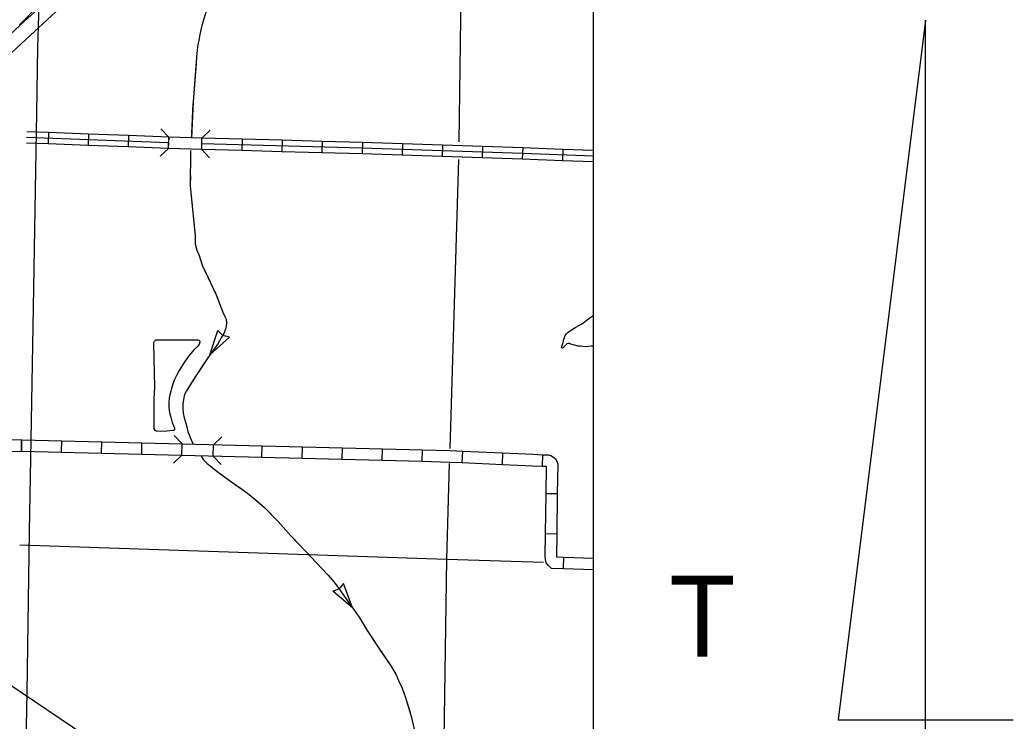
# Model space of a CAD drawing. Extents: x 1196286 to 1268366, y 2040822 to 2082115.
# Drawn here: x 1238759 to 1243663, y 2060409 to 2063873 of the extents above; entities that cross this region are included whole.
import ezdxf

# ---------------------------------------------------------------- set-up
doc = ezdxf.new("R2010")
doc.units = 0
for name, color, linetype in [('26', 7, 'Continuous'), ('60', 7, 'Continuous'), ('61', 7, 'Continuous'), ('62', 7, 'Continuous'), ('Level 71', 7, 'Continuous'), ('Level 8', 7, 'Continuous'), ('Level 81', 7, 'Continuous'), ('Level 83', 7, 'Continuous'), ('Level 84', 7, 'Continuous'), ('Level 87', 7, 'Continuous')]:
    doc.layers.add(name, color=color, linetype=linetype)

msp = doc.modelspace()

# ---------------------------------------------------------------- linework, layer by layer
at = {"layer": '60'}
for points in [[(1240928, 2063270.6), (1240953.2, 2065222)], [(1240882.7, 2061755.5), (1240926.1, 2063183.4)], [(1240836.4, 2059202.8), (1240866.1, 2061210.1), (1240880.5, 2061681.6)], [(1238758.7, 2061280.6), (1240866.1, 2061210.1), (1241344.8, 2061194.4)]]:
    msp.add_lwpolyline(points, dxfattribs=at)
at = {"layer": '61'}
for p, q in [((1238900.1, 2063316.3), (1238898, 2063260.1)), ((1239097.9, 2063308.9), (1239095.8, 2063252.7)), ((1239295.8, 2063301.4), (1239293.7, 2063245.2)), ((1239493.7, 2063294), (1239491.5, 2063237.8)), ((1239855.8, 2063283.7), (1239854.2, 2063227.4)), ((1240053.8, 2063278), (1240052.2, 2063221.8)), ((1240251.7, 2063272.4), (1240250.1, 2063216.1)), ((1240449.6, 2063266.7), (1240448, 2063210.5)), ((1240647.6, 2063260.3), (1240645.8, 2063204.1)), ((1240845.5, 2063253.9), (1240843.7, 2063197.6)), ((1241043.4, 2063247.4), (1241041.6, 2063191.2)), ((1241241.3, 2063241), (1241239.5, 2063184.8)), ((1241439.3, 2063233.4), (1241437.1, 2063177.2)), ((1238766.4, 2061742.2), (1238767.8, 2061798.4)), ((1238964.3, 2061737.2), (1238965.7, 2061793.5)), ((1239162.2, 2061732.3), (1239163.6, 2061788.5)), ((1239360.2, 2061727.3), (1239361.6, 2061783.6)), ((1239558.1, 2061722.4), (1239559.5, 2061778.6)), ((1239713.3, 2061718.1), (1239714.7, 2061774.4)), ((1239954, 2061712.5), (1239955.4, 2061768.7)), ((1240151.9, 2061707.5), (1240153.3, 2061763.7)), ((1240349.9, 2061702.5), (1240351.3, 2061758.8)), ((1240547.8, 2061697.6), (1240549.2, 2061753.8)), ((1240745.7, 2061692.6), (1240747.1, 2061748.9)), ((1240943.1, 2061686.5), (1240945.6, 2061742.7)), ((1241140.9, 2061677.6), (1241143.4, 2061733.8)), ((1241338.9, 2061669.1), (1241341, 2061725.3)), ((1241355.9, 2061533.9), (1241412.1, 2061533.1)), ((1241352.9, 2061336), (1241409.1, 2061335.1)), ((1241442.6, 2061163.1), (1241444.4, 2061219.3))]:
    msp.add_line(p, q, dxfattribs=at)
for points in [[(1239492.6, 2063265.9), (1238791.8, 2063292.2)], [(1238900.1, 2063316.3), (1238792.9, 2063320.3)], [(1239097.9, 2063308.9), (1238900.1, 2063316.3)], [(1239295.8, 2063301.4), (1239097.9, 2063308.9)], [(1239493.7, 2063294), (1239295.8, 2063301.4)], [(1239491.8, 2063237.8), (1239493.4, 2063294)], [(1239657.9, 2063289.3), (1239493.4, 2063294)], [(1239656.3, 2063233.1), (1239657.9, 2063289.3)], [(1239855.8, 2063283.7), (1239657.9, 2063289.3)], [(1240053.8, 2063278), (1239855.8, 2063283.7)], [(1240251.7, 2063272.4), (1240053.8, 2063278)], [(1240449.6, 2063266.7), (1240251.7, 2063272.4)], [(1238898, 2063260.1), (1238790.8, 2063264.1)], [(1239095.8, 2063252.7), (1238898, 2063260.1)], [(1239293.7, 2063245.2), (1239095.8, 2063252.7)], [(1239491.5, 2063237.8), (1239293.7, 2063245.2)], [(1239656.3, 2063233.1), (1239491.8, 2063237.8)], [(1239854.2, 2063227.4), (1239656.3, 2063233.1)], [(1241590.6, 2063199.4), (1241240.4, 2063212.9), (1240448.8, 2063238.6), (1239657.1, 2063261.2)], [(1240052.2, 2063221.8), (1239854.2, 2063227.4)], [(1240647.6, 2063260.3), (1240449.9, 2063266.7), (1240450, 2063266.7)], [(1240845.5, 2063253.9), (1240647.6, 2063260.3)], [(1241043.4, 2063247.4), (1240845.5, 2063253.9)], [(1241241.3, 2063241), (1241043.4, 2063247.4)], [(1241439.3, 2063233.4), (1241241.5, 2063241)], [(1241590.6, 2063227.5), (1241439.3, 2063233.4)], [(1240250.1, 2063216.1), (1240052.2, 2063221.8)], [(1240448, 2063210.5), (1240250.1, 2063216.1)], [(1240645.8, 2063204.1), (1240447.7, 2063210.5), (1240447.6, 2063210.5)], [(1240843.7, 2063197.6), (1240645.8, 2063204.1)], [(1241041.6, 2063191.2), (1240843.7, 2063197.6)], [(1241239.5, 2063184.8), (1241041.6, 2063191.2)], [(1241437.1, 2063177.2), (1241239.3, 2063184.8)], [(1241590.6, 2063171.2), (1241437.1, 2063177.2)], [(1238767.8, 2061798.4), (1238965.7, 2061793.5)], [(1238965.7, 2061793.5), (1239163.6, 2061788.5)], [(1239163.6, 2061788.5), (1239361.6, 2061783.6)], [(1239361.6, 2061783.6), (1239559.5, 2061778.6)], [(1239559.5, 2061778.6), (1239757.5, 2061773.6)], [(1239757.5, 2061773.6), (1239955.4, 2061768.7)], [(1239955.4, 2061768.7), (1240153.3, 2061763.7)], [(1240153.3, 2061763.7), (1240351.3, 2061758.8)], [(1240351.3, 2061758.8), (1240549.2, 2061753.8)], [(1240549.2, 2061753.8), (1240747.1, 2061748.9)], [(1238766.4, 2061742.2), (1238964.3, 2061737.2)], [(1238964.3, 2061737.2), (1239162.2, 2061732.3)], [(1239162.2, 2061732.3), (1239360.2, 2061727.3)], [(1239360.2, 2061727.3), (1239558.1, 2061722.4)], [(1239558.1, 2061722.4), (1239756, 2061717.4)], [(1239756, 2061717.4), (1239954, 2061712.5)], [(1239954, 2061712.5), (1240151.9, 2061707.5)], [(1240151.9, 2061707.5), (1240349.9, 2061702.5)], [(1240349.9, 2061702.5), (1240547.8, 2061697.6)], [(1240747.1, 2061748.9), (1240884, 2061745.4), (1240945.6, 2061742.7)], [(1240945.6, 2061742.7), (1241143.4, 2061733.8)], [(1241143.4, 2061733.8), (1241291.6, 2061727.1), (1241341, 2061725.3)], [(1241341, 2061725.3), (1241366.5, 2061724.3), (1241384, 2061719.8), (1241395.5, 2061710.9), (1241402.7, 2061704.3), (1241409.6, 2061693.6), (1241414.3, 2061678.8), (1241412.1, 2061533.1)], [(1240547.8, 2061697.6), (1240745.7, 2061692.6)], [(1240745.7, 2061692.6), (1240882, 2061689.2), (1240943.1, 2061686.5)], [(1240943.1, 2061686.5), (1241140.9, 2061677.6)], [(1241140.9, 2061677.6), (1241289.3, 2061670.9), (1241338.9, 2061669.1)], [(1241338.9, 2061669.1), (1241357.9, 2061668.4), (1241355.9, 2061533.9)], [(1241355.9, 2061533.9), (1241352.9, 2061336)], [(1241412.1, 2061533.1), (1241409.1, 2061335.1)], [(1241352.9, 2061336), (1241351.1, 2061222.4), (1241351.9, 2061208), (1241355.5, 2061191.1), (1241365.9, 2061180.4), (1241381.7, 2061165.1), (1241442.6, 2061163.1)], [(1241409.1, 2061335.1), (1241407.4, 2061223.5), (1241407.6, 2061220.5), (1241444.4, 2061219.3)], [(1241444.4, 2061219.3), (1241590.6, 2061214.5)], [(1241442.6, 2061163.1), (1241590.6, 2061158.2)]]:
    msp.add_lwpolyline(points, dxfattribs=at)
at = {"layer": '62'}
for p, q in [((1239696.4, 2062218.5), (1239735.8, 2062339.4)), ((1239696.4, 2062218.5), (1239793.1, 2062305.3)), ((1239735.8, 2062339.4), (1239759.7, 2062314.9)), ((1239793.1, 2062305.3), (1239760.1, 2062314.7)), ((1240356, 2061089.5), (1240334.6, 2061062.9)), ((1240401.3, 2060968.6), (1240357, 2061089.5)), ((1240303.2, 2061050.6), (1240334.2, 2061062.6)), ((1240401.3, 2060968.6), (1240303.2, 2061050.6))]:
    msp.add_line(p, q, dxfattribs=at)
for points in [[(1239749.7, 2064160.6), (1239733.5, 2064109.1), (1239690.6, 2063954.2), (1239656.8, 2063845.1), (1239646.5, 2063801.2), (1239642.1, 2063772.6), (1239638.1, 2063749.3), (1239633.2, 2063710.3), (1239613.6, 2063468.2), (1239606, 2063290.9)], [(1239749.7, 2064160.6), (1239733.5, 2064109.1), (1239690.6, 2063954.2), (1239656.8, 2063845.1), (1239646.5, 2063801.2), (1239642.1, 2063772.6), (1239638.1, 2063749.3), (1239633.2, 2063710.3), (1239613.6, 2063468.2), (1239606, 2063290.9)], [(1239658.9, 2063852), (1239656.8, 2063845.1), (1239646.5, 2063801.2), (1239642.1, 2063772.6), (1239638.1, 2063749.3), (1239633.2, 2063710.3), (1239632.8, 2063706)], [(1239628.8, 2063656.6), (1239616.8, 2063508.6)], [(1239613.2, 2063459.3), (1239606.8, 2063310.9)], [(1239601.8, 2063228), (1239600.2, 2063051.8), (1239624.7, 2062806.4), (1239624.6, 2062767.3), (1239631.8, 2062736), (1239643.8, 2062708.8), (1239659, 2062661.6), (1239728.6, 2062514.9), (1239761.4, 2062428.8), (1239770.5, 2062408.3), (1239776.4, 2062394.4), (1239778.8, 2062375.9), (1239777.1, 2062357.9), (1239774, 2062345.5), (1239765.5, 2062324.1), (1239752.1, 2062301.7), (1239735.7, 2062273.3), (1239686.2, 2062204.2), (1239628.7, 2062116.1), (1239581.4, 2062041), (1239574.9, 2062029.8), (1239569.8, 2062015.2), (1239567, 2061996.8), (1239562.7, 2061977.6), (1239562.8, 2061955), (1239564.4, 2061930.9), (1239569.4, 2061907.2), (1239578.5, 2061880.4), (1239587.8, 2061839.7), (1239603.8, 2061798.5), (1239613.2, 2061780.3)], [(1239601.8, 2063228), (1239600.2, 2063051.8), (1239624.7, 2062806.4), (1239624.6, 2062767.3), (1239631.8, 2062736), (1239643.8, 2062708.8), (1239659, 2062661.6), (1239728.6, 2062514.9), (1239761.4, 2062428.8), (1239770.5, 2062408.3), (1239776.4, 2062394.4), (1239778.8, 2062375.9), (1239777.1, 2062357.9), (1239774, 2062345.5), (1239765.5, 2062324.1), (1239752.1, 2062301.7), (1239735.7, 2062273.3), (1239686.2, 2062204.2), (1239628.7, 2062116.1), (1239581.4, 2062041), (1239574.9, 2062029.8), (1239569.8, 2062015.2), (1239567, 2061996.8), (1239562.7, 2061977.6), (1239562.8, 2061955), (1239564.4, 2061930.9), (1239569.4, 2061907.2), (1239578.5, 2061880.4), (1239587.8, 2061839.7), (1239603.8, 2061798.5), (1239613.2, 2061780.3)], [(1239601.8, 2063228), (1239601.1, 2063153.7)], [(1239600.7, 2063104.2), (1239600.2, 2063051.8), (1239609.7, 2062956.2)], [(1239614.6, 2062907), (1239624.7, 2062806.4), (1239624.6, 2062767.3), (1239626.5, 2062759.2)], [(1239642.2, 2062712.5), (1239643.8, 2062708.8), (1239659, 2062661.6), (1239699.7, 2062575.9)], [(1239720.9, 2062531.1), (1239728.6, 2062514.9), (1239761.4, 2062428.8), (1239770.5, 2062408.3), (1239776.4, 2062394.4), (1239776.5, 2062393.5)], [(1241590.6, 2062260.7), (1241579.2, 2062260.5), (1241553.7, 2062258.6), (1241525.6, 2062260.7), (1241515.9, 2062261.6), (1241497.6, 2062265.9), (1241490.9, 2062267.5), (1241478.6, 2062271.8), (1241476.3, 2062272.9), (1241472.6, 2062273.7), (1241470.7, 2062274.1), (1241467.3, 2062274.5), (1241464, 2062274.2), (1241461.3, 2062273.1), (1241456, 2062270.1), (1241454.2, 2062267.9), (1241451.1, 2062264.5), (1241449.2, 2062262.3), (1241446.6, 2062259), (1241443.9, 2062256), (1241442.4, 2062254.9), (1241441.2, 2062253.4), (1241435.6, 2062251.2), (1241433.4, 2062254.2), (1241434.6, 2062259.5), (1241437.3, 2062269.6), (1241440.8, 2062278.6), (1241442.7, 2062286.5), (1241444.7, 2062295.8), (1241447.4, 2062304.8), (1241451.3, 2062313.5), (1241457.4, 2062322), (1241466.1, 2062330.6), (1241480.1, 2062340.2), (1241504.2, 2062355.8), (1241515.5, 2062362), (1241533.6, 2062371.2), (1241552.1, 2062384.6), (1241570.3, 2062399.1), (1241590.6, 2062413.1)], [(1239773.7, 2062344.7), (1239765.5, 2062324.1), (1239752.1, 2062301.7), (1239735.7, 2062273.3), (1239719, 2062249.9)], [(1239424.2, 2062058.2), (1239420.3, 2062273.9), (1239420, 2062276.5), (1239420.4, 2062279.5), (1239421.6, 2062282.9), (1239422.7, 2062285.5), (1239424.2, 2062287.8), (1239430.7, 2062292.2), (1239435.5, 2062292.5), (1239451.3, 2062292.4), (1239549.8, 2062292.4), (1239622.1, 2062292.8), (1239627, 2062292.7), (1239633.8, 2062292.3), (1239637.9, 2062291.8), (1239642.7, 2062291.4), (1239643.9, 2062290.3), (1239645, 2062288), (1239646.4, 2062286.1), (1239647.1, 2062282), (1239646.3, 2062277.8), (1239645.2, 2062274.1), (1239641.3, 2062266.6), (1239634.9, 2062259.1), (1239621.6, 2062245.7), (1239590.5, 2062212.2), (1239567.3, 2062175.2), (1239545.2, 2062141.6), (1239534, 2062119.2), (1239522.5, 2062096.3), (1239515.6, 2062079.1), (1239511.7, 2062068.2), (1239507.1, 2062051.7), (1239503.2, 2062038.6), (1239499.2, 2062021.4), (1239495.7, 2062003.7), (1239494.3, 2061985.3), (1239494.4, 2061959), (1239497.5, 2061933), (1239504, 2061910), (1239510.5, 2061884.7), (1239517, 2061869.9), (1239521.1, 2061861.3), (1239522.9, 2061857.5), (1239522.9, 2061856.3), (1239522.8, 2061849.6), (1239520.5, 2061845.5), (1239513.8, 2061844), (1239485.6, 2061841.3), (1239450.8, 2061840.2), (1239436.5, 2061842.2), (1239431.7, 2061842.3), (1239426.1, 2061844.2), (1239422, 2061852.9), (1239421.5, 2061868.3), (1239421.7, 2061923.6), (1239421.7, 2061956.7), (1239422.1, 2062001.2), (1239424.2, 2062058.2)], [(1239668.7, 2062177.5), (1239628.7, 2062116.1), (1239628.2, 2062115.3)], [(1239628.2, 2062115.3), (1239588.6, 2062052.5)], [(1239568.7, 2062007.7), (1239567, 2061996.8), (1239562.7, 2061977.6), (1239562.8, 2061955), (1239564.4, 2061930.9), (1239569.4, 2061907.2), (1239578.5, 2061880.4), (1239582.6, 2061862.4)], [(1239597.3, 2061815.2), (1239603.8, 2061798.5), (1239613.2, 2061780.3)], [(1239654, 2061717.8), (1239664.2, 2061702.3), (1239684.2, 2061681.8), (1239731.4, 2061643.3), (1239793.8, 2061597.1), (1239882.7, 2061535.5), (1239928, 2061497.1), (1239968.1, 2061462.4), (1240034.4, 2061394.7)], [(1239654, 2061717.8), (1239664.2, 2061702.3), (1239684.2, 2061681.8), (1239705.2, 2061664.6)], [(1239654, 2061717.8), (1239664.2, 2061702.3), (1239684.2, 2061681.8), (1239731.4, 2061643.3), (1239793.8, 2061597.1), (1239882.7, 2061535.5), (1239928, 2061497.1), (1239968.1, 2061462.4), (1240034.4, 2061394.7)], [(1239744, 2061633.9), (1239793.8, 2061597.1), (1239864.9, 2061547.8)], [(1239904, 2061517.5), (1239928, 2061497.1), (1239968.1, 2061462.4), (1240012.8, 2061416.7)], [(1240034.4, 2061394.7), (1240095.8, 2061325.2), (1240171, 2061247.3), (1240222.1, 2061192.9), (1240280.7, 2061129.9), (1240310.3, 2061095.7), (1240353.8, 2061036.1), (1240433.5, 2060922.8), (1240473.3, 2060857.3), (1240524.9, 2060778.9), (1240589.7, 2060682.3), (1240615.1, 2060641.3), (1240628.7, 2060610), (1240645.5, 2060572.9), (1240663, 2060526.1), (1240693, 2060426.5), (1240722.9, 2060289.2)], [(1240034.4, 2061394.7), (1240095.8, 2061325.2), (1240171, 2061247.3), (1240222.1, 2061192.9), (1240280.7, 2061129.9), (1240310.3, 2061095.7), (1240353.8, 2061036.1), (1240433.5, 2060922.8), (1240473.3, 2060857.3), (1240524.9, 2060778.9), (1240589.7, 2060682.3), (1240615.1, 2060641.3), (1240628.7, 2060610), (1240645.5, 2060572.9), (1240663, 2060526.1), (1240693, 2060426.5), (1240722.9, 2060289.2)], [(1240046.8, 2061380.7), (1240095.8, 2061325.2), (1240147.5, 2061271.6)], [(1240181.8, 2061235.9), (1240222.1, 2061192.9), (1240280.7, 2061129.9), (1240283, 2061127.2)], [(1240314.9, 2061089.4), (1240353.8, 2061036.1), (1240401.3, 2060968.6)], [(1240429.8, 2060928.1), (1240433.5, 2060922.8), (1240468.6, 2060864.9)], [(1240468.6, 2060864.9), (1240473.3, 2060857.3), (1240509.2, 2060802.7)], [(1240536.5, 2060761.5), (1240589.7, 2060682.3), (1240615.1, 2060641.3), (1240617.1, 2060636.8)], [(1240637, 2060591.5), (1240645.5, 2060572.9), (1240663, 2060526.1), (1240685.5, 2060451.3)]]:
    msp.add_lwpolyline(points, dxfattribs=at)
at = {"layer": 'Level 71'}
for p, q in [((1238766.9, 2061798.4), (1238767.2, 2061742.2)), ((1238767.2, 2061742.2), (1238766.9, 2061798.4))]:
    msp.add_line(p, q, dxfattribs=at)
for points in [[(1238766.9, 2061798.4), (1238568.9, 2061797.4)], [(1238569.2, 2061741.1), (1238767.2, 2061742.2)]]:
    msp.add_lwpolyline(points, dxfattribs=at)
at = {"layer": 'Level 8'}
for p, q in [((1243230.8, 2063871.2), (1242798.8, 2060415.2)), ((1243230.8, 2058255.2), (1243230.8, 2063871.2)), ((1243606.9, 2057283.5), (1236659.6, 2061971.8)), ((1242798.8, 2060415.2), (1243662.8, 2060415.2))]:
    msp.add_line(p, q, dxfattribs=at)
msp.add_lwpolyline([(1241590.6, 2065596.8), (1214332.8, 2065596.8), (1214332.8, 2047966.3), (1241590.6, 2047966.3)], close=True, dxfattribs=at)
at = {"layer": 'Level 81'}
msp.add_lwpolyline([(1240757.7, 2065596.8), (1240486.9, 2065346.1), (1239022.5, 2063993.4), (1236837.6, 2061976.6), (1235905.3, 2061125.6), (1235621.7, 2060865.7), (1235429, 2060684.3)], dxfattribs=at)
msp.add_lwpolyline([(1240757.7, 2065596.8), (1240486.9, 2065346.1), (1239022.5, 2063993.4), (1236837.6, 2061976.6), (1235905.3, 2061125.6), (1235621.7, 2060865.7), (1235429, 2060684.3)], dxfattribs=at)
msp.add_lwpolyline([(1240757.7, 2065596.8), (1240486.9, 2065346.1), (1239022.5, 2063993.4), (1236837.6, 2061976.6), (1235905.3, 2061125.6), (1235621.7, 2060865.7), (1235429, 2060684.3)], dxfattribs=at)
at = {"layer": 'Level 83'}
for points in [[(1239454.8, 2063334.9), (1239493.4, 2063294)], [(1239657.9, 2063289.3), (1239698.8, 2063327.9)], [(1239491.8, 2063237.8), (1239450.9, 2063199.2)], [(1239694.9, 2063192.2), (1239656.3, 2063233.1)], [(1239520.8, 2061819.4), (1239559.5, 2061778.6)], [(1239714.7, 2061774.4), (1239755.5, 2061813.1)], [(1239558.1, 2061722.4), (1239517.3, 2061683.6)], [(1239752.1, 2061677.4), (1239713.3, 2061718.1)]]:
    msp.add_lwpolyline(points, dxfattribs=at)
at = {"layer": 'Level 84'}
msp.add_lwpolyline([(1236551.3, 2061808.6), (1237092.9, 2062306.5), (1238170.3, 2063298.4), (1238783.9, 2063867.4), (1238940.5, 2064011.8), (1239110.1, 2064165.4), (1239223.3, 2064269.1), (1239265.3, 2064309.9)], dxfattribs=at)
at = {"layer": 'Level 87'}
for p, q in [((1238853.5, 2063946.7), (1238756.2, 2063847.6)), ((1238847.9, 2063735.9), (1238853.5, 2063946.7)), ((1238842, 2063414.1), (1238847.9, 2063735.9)), ((1238838.7, 2063225.3), (1238842, 2063414.1)), ((1238827.2, 2062547.3), (1238838.7, 2063225.3)), ((1238816, 2061892.7), (1238827.2, 2062547.3)), ((1238812.9, 2061706), (1238816, 2061892.7)), ((1238806.7, 2061345.4), (1238812.9, 2061706)), ((1238794, 2060550.9), (1238806.7, 2061345.4)), ((1238783, 2059860.2), (1238794, 2060550.9))]:
    msp.add_line(p, q, dxfattribs=at)

# ---------------------------------------------------------------- texts
at = {"layer": '26'}
msp.add_text('T', height=400, dxfattribs=at).set_placement((1241965.6, 2060728.3))

doc.saveas('drawing.dxf')
